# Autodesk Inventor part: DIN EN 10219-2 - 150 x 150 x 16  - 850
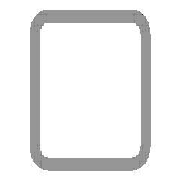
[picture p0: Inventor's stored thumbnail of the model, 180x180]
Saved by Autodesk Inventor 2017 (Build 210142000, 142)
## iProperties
IsCustomPart: 1
Created: 2017-11
Part Number: DIN EN 10219-2 - 150 x 150 x 16  - 850
Material: Steel, Mild
Description: Cold formed welded structural hollow sections of non-alloy and fine grain structural steel
Document SubType Name: Modeling
Standard: DIN
Designer: iusti
Standard Revision: 2006-07
Standards Organization: DIN
Language: en-US
Size Designation: 150 x 150 x 16
Categories: <MemberInstance><Categories><Category DisplayName="Structural Shapes" InternalName="089c4875-fa83-4c05-b084-43b9cc11f5ed" Mnemonic="GRDR"><CategoryParameter Dis
Stock Number: 150 x 150 x 16
Mass: 49891.9 g
Surface Area: 8094.11 cm^2
Volume: 6355.65 cm^3
Density: 7.85 g/cm^3
Appearance: Semi-Polished
_CCFamilyMember: 76
_CCFamilyDisplayName: DIN EN 10219-2 (Square Hollow Section - Cold Formed) - Cold formed welded structural hollow sections of non-alloy and fine grain structural steel
_FrameMemberDoc: Frame Member File
_Version: 15.0.0
_GetPNFromCC: 1
G_L: 850.000 mm
G_W: 150.000 mm
G_H: 150.000 mm
+283E1D8B-273E-42A8-8E91-D86861E19284+CUTDETAIL1: Cut
+7AC7364C-9462-4BE7-8F37-816BA4E0C8A9+CUTDETAIL2: Cut
Author: iusti
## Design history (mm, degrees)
node "Start plane"
node "End plane"
sketch "Sketch"
  geometry: L1 (-75, -27)-(-75, 27); L2 (-27, 75)-(27, 75); L3 (75, 27)-(75, -27); L4 (27, -75)-(-27, -75); L5 (-27, 59)-(27, 59); L6 (59, 27)-(59, -27); L7 (27, -59)-(-27, -59); L8 (-59, -27)-(-59, 27); L9 (0, 118.918)-(0, -118.918) reference; L10 (-118.918, 0)-(118.918, 0) reference; A1 r 48 centre (-27, -27) between (-75, -27) and (-27, -75); A2 r 48 centre (-27, 27) between (-27, 75) and (-75, 27); A3 r 48 centre (27, 27) between (75, 27) and (27, 75); A4 r 48 centre (27, -27) between (27, -75) and (75, -27); A5 r 32 centre (-27, 27) between (-27, 59) and (-59, 27); A6 r 32 centre (27, 27) between (59, 27) and (27, 59); A7 r 32 centre (27, -27) between (27, -59) and (59, -27); A8 r 32 centre (-27, -27) between (-59, -27) and (-27, -59)
  constraints: 16 end point, 16 point on circle, 8 centre point, 8 tangent, 4 parallel, 3 equal radius, 2 perpendicular, 7 other
  dimensions: "d7" = 48 radius of A1 (= G_IR); "d10" = 150 distance between parallel lines of L2 L4 (= G_H); "d11" = 150 distance between parallel lines of L1 L3 (= G_W); "d12" = 16 distance between parallel lines of L3 L6 (= G_T); "d15" = 75 distance between parallel lines of L2 L10 (= 0.5 x d10); "d16" = 75 distance between parallel lines of L9 L3 (= 0.5 x d11)
extrude "Body" new body sketch "Sketch" stored distance "d3" = 850 (= G_L); taper "d4" = 0 deg
node "Driven Length"
  sketch "Sketch3"
    geometry: L1 (0, 0)-(10, 0) reference
    constraints: 2 end point, 1 horizontal
  workplane "Work Plane3"
  sketch "Sketch4"
    geometry: L1 (-2, 75)-(12, 75) reference; L2 (-2, 925)-(12, 925) reference
    dimensions: "d18" = 850 distance between parallel lines of L1 L2 (derived)
workplane "Work Plane4"
split "Split1"
workplane "Work Plane5"
split "Split2"
body "Solid1"
other parameters: "G_W" = 150 [user parameter; used in 1 equation term], "G_H" = 150 [user parameter; used in 1 equation term], "G_T" = 16 [user parameter; used in 1 equation term], "G_IR" = 48 [user parameter; used in 1 equation term], "G_L" = 850 (= d18) [user parameter; used in 1 equation term], "G_OFFSET_START" = -75 [user parameter; used in 1 equation term], "G_OFFSET_END" = -75 [user parameter; used in 1 equation term], "d13" = 75 (= -G_OFFSET_START), "d14" = 925 (= G_OFFSET_END + B_L), "d17" = 90 deg
